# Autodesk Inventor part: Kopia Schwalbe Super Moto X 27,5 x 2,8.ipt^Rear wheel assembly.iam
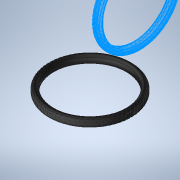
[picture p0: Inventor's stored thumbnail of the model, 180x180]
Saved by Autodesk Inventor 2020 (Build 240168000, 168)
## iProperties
Created: 2017-09
Part Number: Kopia Schwalbe Super Moto X 27,5 x 2,8.ipt^Rear wheel assembly.iam
Material: solidworks materials|BUTYL|223
Document SubType Name: Modeling
Designer: Tomasz
Density: 1.1592 g/cm^3
Appearance: 76,76,76
Sending System: SolidWorks 2017
Last Author: Tomasz
Last Saved: 2017-11-20
Author: Tomasz
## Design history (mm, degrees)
derived "Schwalbe Super Moto X 27,5 x 2,8.ipt"
sketch "Esquisse1"
  geometry: C1 r 298.363 at (0, -293.4) reference; C2 r 342.593 at (0, -293.4); 1 further point
  constraints: 1 centre point, 1 coincident
feature "SrfExtrusion1" sketch "Esquisse1" dims "d0" = 10, "d1" = 0
node "Bryła1"
body "Srf1"
